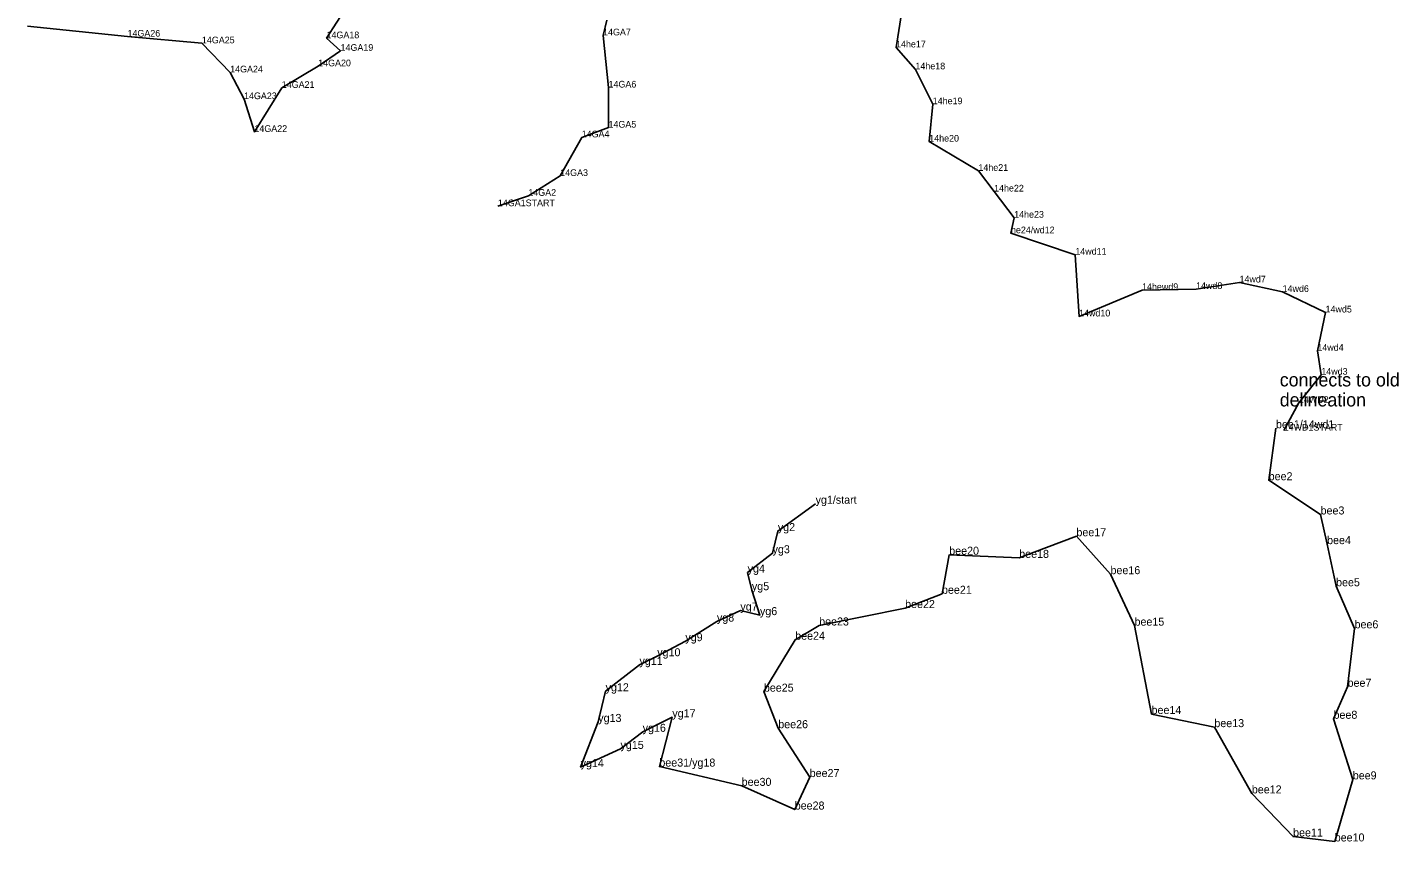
# Model space of a CAD drawing. Extents: x 2072529 to 2267990, y 436423 to 470008.
# Drawn here: x 2256342 to 2257370, y 441160 to 441770 of the extents above; entities that cross this region are included whole.
import ezdxf

# ---------------------------------------------------------------- set-up
doc = ezdxf.new("R2010")
doc.units = 0
doc.layers.add('Level 3', color=7, linetype='Continuous')
doc.layers.add('Old_Level_52', color=7, linetype='Continuous')

msp = doc.modelspace()

# ---------------------------------------------------------------- linework, layer by layer
at = {"layer": 'Level 3'}
for p, q in [((2256417.282, 441763.183), (2256417.282, 441763.183)), ((2256473.074, 441758.157), (2256473.074, 441758.157)), ((2256566.509, 441761.957), (2256566.509, 441761.957)), ((2256773.834, 441764.094), (2256773.834, 441764.094)), ((2256577.024, 441752.542), (2256577.024, 441752.542)), ((2256993.448, 441755.079), (2256993.448, 441755.079)), ((2256560.246, 441740.959), (2256560.246, 441740.959)), ((2257007.999, 441738.662), (2257007.999, 441738.662)), ((2256494.249, 441736.363), (2256494.249, 441736.363)), ((2256532.959, 441724.8), (2256532.959, 441724.8)), ((2256777.939, 441725.047), (2256777.939, 441725.047)), ((2256504.63, 441716.339), (2256504.63, 441716.339)), ((2257021.011, 441712.542), (2257021.011, 441712.542)), ((2256512.442, 441691.794), (2256512.442, 441691.794)), ((2256757.783, 441687.723), (2256757.783, 441687.723)), ((2256777.89, 441695.006), (2256777.89, 441695.006)), ((2257018.354, 441684.528), (2257018.354, 441684.528)), ((2256741.693, 441658.771), (2256741.693, 441658.771)), ((2257055.233, 441662.611), (2257055.233, 441662.611)), ((2257066.978, 441647.144), (2257066.978, 441647.144)), ((2256694.973, 441636.145), (2256694.973, 441636.145)), ((2256717.802, 441643.918), (2256717.802, 441643.918)), ((2257082.039, 441627.524), (2257082.039, 441627.524)), ((2257079.647, 441615.883), (2257079.647, 441615.883)), ((2257127.888, 441599.821), (2257127.888, 441599.821)), ((2257177.892, 441573.359), (2257177.892, 441573.359)), ((2257218.413, 441574.116), (2257218.413, 441574.116)), ((2257250.977, 441578.994), (2257250.977, 441578.994)), ((2257283.293, 441571.913), (2257283.293, 441571.913)), ((2257130.676, 441553.562), (2257130.676, 441553.562)), ((2257315.501, 441556.531), (2257315.501, 441556.531)), ((2257309.351, 441527.841), (2257309.351, 441527.841)), ((2257312.312, 441509.907), (2257312.312, 441509.907)), ((2257295.548, 441488.76), (2257295.548, 441488.76)), ((2257278.335, 441469.816), (2257278.335, 441469.816)), ((2257284.108, 441468.069), (2257284.108, 441468.069)), ((2257272.862, 441430.855), (2257272.862, 441430.855)), ((2256933.169, 441413.269), (2256933.169, 441413.269)), ((2257311.779, 441405.231), (2257311.779, 441405.231)), ((2256904.844, 441392.772), (2256904.844, 441392.772)), ((2257128.72, 441388.918), (2257128.72, 441388.918)), ((2257316.645, 441382.995), (2257316.645, 441382.995)), ((2256900.918, 441376.167), (2256900.918, 441376.167)), ((2257033.362, 441375.059), (2257033.362, 441375.059)), ((2257085.831, 441372.693), (2257085.831, 441372.693)), ((2256882.21, 441361.715), (2256882.21, 441361.715)), ((2257154.253, 441360.486), (2257154.253, 441360.486)), ((2256885.415, 441348.49), (2256885.415, 441348.49)), ((2257323.391, 441351.433), (2257323.391, 441351.433)), ((2257027.937, 441345.805), (2257027.937, 441345.805)), ((2256876.778, 441333.229), (2256876.778, 441333.229)), ((2256891.444, 441329.82), (2256891.444, 441329.82)), ((2257000.285, 441335.125), (2257000.285, 441335.125)), ((2256859.194, 441325.009), (2256859.194, 441325.009)), ((2256935.845, 441322.052), (2256935.845, 441322.052)), ((2257172.268, 441321.927), (2257172.268, 441321.927)), ((2257337.23, 441319.92), (2257337.23, 441319.92)), ((2256835.533, 441310.294), (2256835.533, 441310.294)), ((2256917.858, 441311.368), (2256917.858, 441311.368)), ((2256814.432, 441299.004), (2256814.432, 441299.004)), ((2256801.108, 441292.571), (2256801.108, 441292.571)), ((2257332.021, 441276.15), (2257332.021, 441276.15)), ((2256775.741, 441272.765), (2256775.741, 441272.765)), ((2256894.388, 441272.478), (2256894.388, 441272.478)), ((2257185.051, 441255.731), (2257185.051, 441255.731)), ((2256770.218, 441249.81), (2256770.218, 441249.81)), ((2256825.747, 441253.297), (2256825.747, 441253.297)), ((2256905.17, 441245.102), (2256905.17, 441245.102)), ((2257232.132, 441245.904), (2257232.132, 441245.904)), ((2257321.468, 441252.175), (2257321.468, 441252.175)), ((2256803.516, 441242.392), (2256803.516, 441242.392)), ((2256786.901, 441229.625), (2256786.901, 441229.625)), ((2256757, 441215.969), (2256757, 441215.969)), ((2256816.045, 441216.367), (2256816.045, 441216.367)), ((2256928.737, 441208.504), (2256928.737, 441208.504)), ((2257335.897, 441206.768), (2257335.897, 441206.768)), ((2256877.754, 441201.91), (2256877.754, 441201.91)), ((2257260.215, 441196.265), (2257260.215, 441196.265)), ((2256917.523, 441184.175), (2256917.523, 441184.175)), ((2257291.167, 441163.968), (2257291.167, 441163.968)), ((2257322.367, 441160.28), (2257322.367, 441160.28))]:
    msp.add_line(p, q, dxfattribs=at)
at = {"layer": 'Old_Level_52'}
for points in [[(2256999.573, 441793.49), (2256993.448, 441755.079), (2257007.999, 441738.662), (2257021.011, 441712.542), (2257018.354, 441684.528), (2257055.233, 441662.611), (2257066.978, 441647.144), (2257082.039, 441627.524), (2257079.647, 441615.883), (2257127.888, 441599.821), (2257130.676, 441553.562), (2257177.892, 441573.359), (2257218.413, 441574.116), (2257250.977, 441578.994), (2257283.293, 441571.913), (2257315.501, 441556.531), (2257309.351, 441527.841), (2257312.312, 441509.907)], [(2256582.031, 441785.909), (2256566.509, 441761.957), (2256577.024, 441752.542), (2256560.246, 441740.959), (2256532.959, 441724.8), (2256512.442, 441691.794), (2256504.63, 441716.339), (2256494.249, 441736.363), (2256473.074, 441758.157), (2256417.282, 441763.183), (2256342.251, 441771.007)], [(2256694.973, 441636.145), (2256717.802, 441643.918), (2256741.693, 441658.771), (2256757.783, 441687.723), (2256777.89, 441695.006), (2256777.939, 441725.047), (2256773.834, 441764.094), (2256776.718, 441775.529)], [(2257312.312, 441509.907), (2257295.548, 441488.76), (2257284.108, 441468.069)], [(2256933.169, 441413.269), (2256904.844, 441392.772), (2256900.918, 441376.167), (2256882.21, 441361.715), (2256885.415, 441348.49), (2256891.444, 441329.82), (2256876.778, 441333.229), (2256859.194, 441325.009), (2256835.533, 441310.294), (2256814.432, 441299.004), (2256801.108, 441292.571), (2256775.741, 441272.765), (2256770.218, 441249.81), (2256757, 441215.969), (2256786.901, 441229.625), (2256803.516, 441242.392), (2256825.747, 441253.297), (2256816.045, 441216.367), (2256877.754, 441201.91), (2256917.523, 441184.175), (2256928.737, 441208.504), (2256905.17, 441245.102), (2256894.388, 441272.478), (2256917.858, 441311.368), (2256935.845, 441322.052), (2257000.285, 441335.125), (2257027.937, 441345.805), (2257033.362, 441375.059), (2257085.831, 441372.693), (2257128.72, 441388.918), (2257154.253, 441360.486), (2257172.268, 441321.927), (2257185.051, 441255.731), (2257232.132, 441245.904), (2257260.215, 441196.265), (2257291.167, 441163.968), (2257322.367, 441160.28), (2257335.897, 441206.768), (2257321.468, 441252.175), (2257332.021, 441276.15), (2257337.23, 441319.92), (2257323.391, 441351.433), (2257316.645, 441382.995), (2257311.779, 441405.231), (2257272.862, 441430.855), (2257278.335, 441469.816)]]:
    msp.add_lwpolyline(points, dxfattribs=at)

# ---------------------------------------------------------------- texts
for s, height, p in [('14GA7', 5, (2256773.834, 441764.094)), ('14GA26', 5, (2256417.282, 441763.183)), ('14GA25', 5, (2256473.074, 441758.157)), ('14GA18', 5, (2256566.509, 441761.957)), ('14he17', 5, (2256993.448, 441755.079)), ('14GA19', 5, (2256577.024, 441752.542)), ('14GA24', 5, (2256494.249, 441736.363)), ('14GA20', 5, (2256560.246, 441740.959)), ('14he18', 5, (2257007.999, 441738.662)), ('14GA21', 5, (2256532.959, 441724.8)), ('14GA6', 5, (2256777.939, 441725.047)), ('14GA23', 5, (2256504.63, 441716.339)), ('14he19', 5, (2257021.011, 441712.542)), ('14GA22', 5, (2256512.442, 441691.794)), ('14GA5', 5, (2256777.89, 441695.006)), ('14GA4', 5, (2256757.783, 441687.723)), ('14he20', 5, (2257018.354, 441684.528)), ('14he21', 5, (2257055.233, 441662.611)), ('14GA3', 5, (2256741.693, 441658.771)), ('14GA2', 5, (2256717.802, 441643.918)), ('14he22', 5, (2257066.978, 441647.144)), ('14GA1START', 5, (2256694.973, 441636.145)), ('14he23', 5, (2257082.039, 441627.524)), ('he24/wd12', 5, (2257079.647, 441615.883)), ('14wd11', 5, (2257127.888, 441599.821)), ('14wd7', 5, (2257250.977, 441578.994)), ('14hewd9', 5, (2257177.892, 441573.359)), ('14wd8', 5, (2257218.413, 441574.116)), ('14wd6', 5, (2257283.293, 441571.913)), ('14wd10', 5, (2257130.676, 441553.562)), ('14wd5', 5, (2257315.501, 441556.531)), ('14wd4', 5, (2257309.351, 441527.841)), ('14wd3', 5, (2257312.312, 441509.907)), ('14WD2', 5, (2257295.548, 441488.76)), ('bee1/14wd1', 6, (2257278.335, 441469.816)), ('14WD1START', 5, (2257284.108, 441468.069)), ('bee2', 6, (2257272.862, 441430.855)), ('yg1/start', 6, (2256933.169, 441413.269)), ('bee3', 6, (2257311.779, 441405.231)), ('yg2', 6, (2256904.844, 441392.772)), ('bee17', 6, (2257128.72, 441388.918)), ('bee4', 6, (2257316.645, 441382.995)), ('yg3', 6, (2256900.918, 441376.167)), ('bee20', 6, (2257033.362, 441375.059)), ('bee18', 6, (2257085.831, 441372.693)), ('yg4', 6, (2256882.21, 441361.715)), ('bee16', 6, (2257154.253, 441360.486)), ('bee5', 6, (2257323.391, 441351.433)), ('yg5', 6, (2256885.415, 441348.49)), ('bee21', 6, (2257027.937, 441345.805)), ('yg7', 6, (2256876.778, 441333.229)), ('bee22', 6, (2257000.285, 441335.125)), ('yg8', 6, (2256859.194, 441325.009)), ('yg6', 6, (2256891.444, 441329.82)), ('bee23', 6, (2256935.845, 441322.052)), ('bee15', 6, (2257172.268, 441321.927)), ('yg9', 6, (2256835.533, 441310.294)), ('bee24', 6, (2256917.858, 441311.368)), ('bee6', 6, (2257337.23, 441319.92)), ('yg11', 6, (2256801.108, 441292.571)), ('yg10', 6, (2256814.432, 441299.004)), ('yg12', 6, (2256775.741, 441272.765)), ('bee25', 6, (2256894.388, 441272.478)), ('bee7', 6, (2257332.021, 441276.15)), ('yg13', 6, (2256770.218, 441249.81)), ('yg17', 6, (2256825.747, 441253.297)), ('bee14', 6, (2257185.051, 441255.731)), ('bee8', 6, (2257321.468, 441252.175)), ('yg16', 6, (2256803.516, 441242.392)), ('bee26', 6, (2256905.17, 441245.102)), ('bee13', 6, (2257232.132, 441245.904)), ('yg15', 6, (2256786.901, 441229.625)), ('yg14', 6, (2256757, 441215.969)), ('bee31/yg18', 6, (2256816.045, 441216.367)), ('bee27', 6, (2256928.737, 441208.504)), ('bee30', 6, (2256877.754, 441201.91)), ('bee9', 6, (2257335.897, 441206.768)), ('bee12', 6, (2257260.215, 441196.265)), ('bee28', 6, (2256917.523, 441184.175)), ('bee11', 6, (2257291.167, 441163.968)), ('bee10', 6, (2257322.367, 441160.28))]:
    msp.add_text(s, height=height).set_placement(p)
for s, p in [('connects to old', (2257281.153, 441501.133)), ('delineation', (2257281.153, 441486.133))]:
    msp.add_text(s, height=10, dxfattribs=at).set_placement(p)

doc.saveas('drawing.dxf')
